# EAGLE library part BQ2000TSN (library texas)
CHARGE MANAGEMENT IC
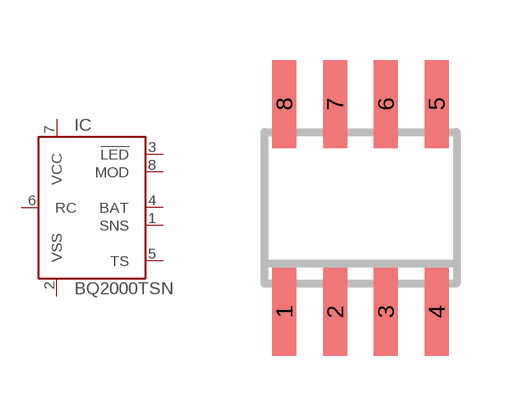
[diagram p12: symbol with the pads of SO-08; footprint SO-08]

Designator prefix IC

## BQ2000TSN (MF: TEXAS INSTRUMENT CONNECTORS; MPN: BQ2000TSN-B5; OC_FARNELL: 1212295; OC_NEWARK: 74C7508)  [SO-08]
1  SNS  in
2  VSS  pwr
3  !LED  out
4  BAT  in
5  TS  in
6  RC  in
7  VCC  in
8  MOD  out

## Footprint SO-08 (pad centres in mm)
D (R-PDSO-G8) Plastic Small Outline Package Source: http://focus.ti.com/lit/ds/symlink/sn65als176.pdf
smd 0.6 x 2.2: 1 -1.905,-2.6; 2 -0.635,-2.6; 3 0.635,-2.6; 4 1.905,-2.6; 5 1.905,2.6; 6 0.635,2.6; 7 -0.635,2.6; 8 -1.905,2.6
